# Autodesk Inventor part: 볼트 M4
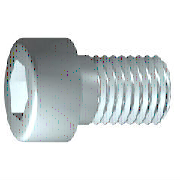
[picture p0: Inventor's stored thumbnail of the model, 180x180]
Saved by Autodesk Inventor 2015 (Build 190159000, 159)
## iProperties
IsCustomPart: 0
Created: 2016-04
Part Number: 볼트 M4
Material: 강철, 연강
Description: 6각머리 태핑 나사
Document SubType Name: Modeling
Standard: KS B 1003
Designer: mdu
Standards Organization: KS
Language: ko-KR
Size Designation: M 4 x 10
Categories: <MemberInstance><Categories><Category DisplayName="조임쇠" InternalName="e4da775c-781d-43d5-af7c-5136215cf5a6" Mnemonic="FSTN"><Category DisplayName="볼트" InternalN
Density: 7.86 g/cm^3
Mass: 2.0371 g
Surface Area: 3.0572 cm^2
Volume: 0.259174 cm^3
Appearance: 금속 1800F 열
Author: mdu
Revision Number: 1
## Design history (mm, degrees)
sketch "스케치1"
  geometry: L1 (-1, 0)-(10, 0); L2 (10, 0)-(10, 2); L3 (10, 2)-(1.75, 2); L4 (1.75, 2)-(1.32, 2); L5 (1.32, 2)-(0, 2); L6 (0, 2)-(0, 3.5); L7 (0, 3.5)-(-4, 3.5); L8 (-4, 3.5)-(-4, 1.732); L9 (-4, 1.732)-(-2, 1.732); L10 (-2, 1.732)-(-1, 0); L11 (-6.8, 0)-(12.8, 0) reference; L12 (0, -0.7)-(0, 4.2) reference; L13 (1.75, 2)-(0, 2)
  constraints: 22 end point, 6 parallel, 2 collinear, 2 perpendicular, 1 horizontal, 1 point on line
  dimensions: "d1" = 8.25 distance from line of L3.end L2 (= GEL); "d2" = 0.42952 distance of L4.end L3.end (computed from GAL); "d3" = 4 distance between parallel lines of L8 L6 (= KOH); "d4" = 2 distance of L8.end L9.end (= INTI); "d5" = 60 deg angle of L10 L1; "d6" = 4 diameter of L3 L1 (= GD); "d7" = 4 diameter of L5 L1 (= BDM); "d8" = 3.4641 diameter of L9 L1 (= 1.1547 x SW); "d9" = 7 diameter of L7 L1 (= KOD); "d26" = 10 distance between parallel lines of L12 L2 (= NLG)
revolve "본체" sketch "스케치1" stored, may be unused: angle "d10" = 90 deg
sketch "스케치2"
  geometry: L1 (0, -4.9)-(0, 4.9) reference; L2 (-4.9, 0)-(4.9, 0) reference; L3 (1.732, 0)-(0.866, -1.5); L4 (0.866, -1.5)-(-0.866, -1.5); L5 (-0.866, -1.5)-(-1.732, 0); L6 (-1.732, 0)-(-0.866, 1.5); L7 (-0.866, 1.5)-(0.866, 1.5); L8 (0.866, 1.5)-(1.732, 0); 2 further points
  constraints: 12 end point, 1 coincident, 1 horizontal alignment, 1 point on line, 12 other
extrude "슬롯" join sketch "스케치2" stored distance "d11" = 10; taper "d12" = 0 deg
workplane "Work Plane1"
fillet "Fillet2" dims "d30" = 0.1 (= R)
body "Solid1"
fillet "모깎기1" dims "d17" = 0.4 (= RR)
feature "스레드" dims "d13" = 8.25 (= GEL), "d14" = 0
chamfer "모따기1" distance "d15" = 0.42941 (= -0.5 x SPD + 0.5 x GD); stored, may be unused: second distance "d16" = 0.42941 (= GUL), angle "d27" = 45 deg
other parameters: "GD" = 4 (= NND) [user parameter; used in 2 equation terms], "NLG" = 10 [user parameter; used in 1 equation term], "GEL" = 8.25 [user parameter; used in 2 equation terms], "KOD" = 7 [user parameter; used in 1 equation term], "KOH" = 4 [user parameter; used in 1 equation term], "INTI" = 2 [user parameter; used in 1 equation term], "GAL" = 0.42941 (= 0.61345 x PTC) [user parameter; used in 1 equation term], "GUL" = 0.42941 (= 0.61345 x PTC) [user parameter; used in 1 equation term], "BDM" = 4 (= NND) [user parameter; used in 1 equation term], "SW" = 3 [user parameter; used in 2 equation terms], "RR" = 0.4 [user parameter; used in 1 equation term], "SPD" = 3.14117 (= NND - 1.2269 x PTC) [user parameter; used in 1 equation term], "d19" = 0, "d28" = 0, "d29" = 0, "R" = 0.1 [user parameter; used in 1 equation term], "PHH" = 0.2 [user parameter], "GD1" = 3.14117 (= THREADDIA - 1.2269 x PTC) [user parameter], "THREADDIA" = 4 [user parameter; used in 1 equation term], "FAWI" = 45 deg [user parameter], "TPU" = 14.28571 (computed from PTC) [user parameter], "PTC" = 0.7 [user parameter; used in 5 equation terms], "NND" = 4 [user parameter; used in 3 equation terms], "TOA" = 30 deg [user parameter], "E0" = 3.465 (= 1.155 x SW) [user parameter]
